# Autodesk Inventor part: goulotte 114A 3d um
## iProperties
Shininess: 21.0
Length Units: 11269
Angle Units: 11279
Time Units: 11290
Mass Units: 11283
Length Display Precision: 3
Angle Display Precision: 2
Created: 2001-03
Part Number: goulotte 114A 3d um
Material: Par défaut
Document SubType Name: Modélisation
Designer: jost
Density: 0.0
Volumn: 0.0
Area: 0.0
PropertySet Name: Model Information
Control State: 0
Master: False
Checked Out: False
Author: jost
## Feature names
1. Extrusion1
2. Congé1 [Fillet]
3. Extrusion2
4. Congé2 [Fillet]
5. Extrusion3
6. Extrusion4
7. Perçage1 [Hole]
